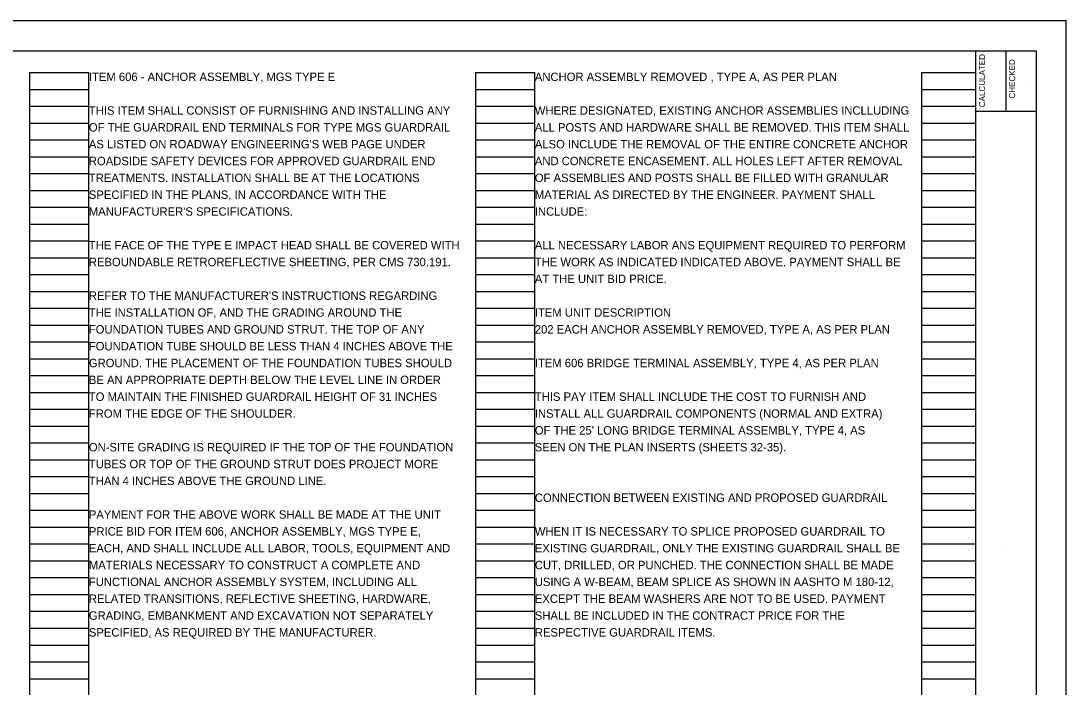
# Model space of a CAD drawing. Extents: x 0 to 34, y 0 to 22.
# Drawn here: x 16.61 to 34, y 10.92 to 22 of the extents above; entities that cross this region are included whole.
import ezdxf

# ---------------------------------------------------------------- set-up
doc = ezdxf.new("R2010")
doc.units = 0
for name, color, linetype in [('SH_Border', 7, 'Continuous'), ('SH_Cut_Line', 7, 'Continuous'), ('SH_Data', 7, 'Continuous'), ('SH_Text', 7, 'Continuous')]:
    doc.layers.add(name, color=color, linetype=linetype)

msp = doc.modelspace()

# ---------------------------------------------------------------- linework, layer by layer
at = {"layer": 'SH_Border'}
for p, q in [((32.5, 0.5), (32.5, 21.5)), ((33, 21.5), (33, 20.5)), ((32.5, 20.5), (33.5, 20.5))]:
    msp.add_line(p, q, dxfattribs=at)
msp.add_lwpolyline([(2, 21.5), (33.5, 21.5), (33.5, 0.5), (2, 0.5)], close=True, dxfattribs=at)
at = {"layer": 'SH_Cut_Line'}
msp.add_lwpolyline([(0, 0), (34, 0), (34, 22), (0, 22)], close=True, dxfattribs=at)
at = {"layer": 'SH_Data'}
for p, q in [((16.76, 0.98), (16.76, 21.14)), ((16.76, 21.14), (17.74, 21.14)), ((17.74, 0.98), (17.74, 21.14)), ((24.18, 0.98), (24.18, 21.14)), ((24.18, 21.14), (25.16, 21.14)), ((25.16, 0.98), (25.16, 21.14)), ((31.6, 0.98), (31.6, 21.14)), ((31.6, 21.14), (32.5, 21.14)), ((32.5, 0.98), (32.5, 21.14)), ((32.92, 21.004), (32.92, 21.004)), ((33.42, 21.004), (33.42, 21.004)), ((16.76, 20.86), (17.74, 20.86)), ((24.18, 20.86), (25.16, 20.86)), ((31.6, 20.86), (32.5, 20.86)), ((16.76, 20.58), (17.74, 20.58)), ((24.18, 20.58), (25.16, 20.58)), ((31.6, 20.58), (32.5, 20.58)), ((16.76, 20.3), (17.74, 20.3)), ((24.18, 20.3), (25.16, 20.3)), ((31.6, 20.3), (32.5, 20.3)), ((16.76, 20.02), (17.74, 20.02)), ((24.18, 20.02), (25.16, 20.02)), ((31.6, 20.02), (32.5, 20.02)), ((16.76, 19.74), (17.74, 19.74)), ((24.18, 19.74), (25.16, 19.74)), ((31.6, 19.74), (32.5, 19.74)), ((16.76, 19.46), (17.74, 19.46)), ((24.18, 19.46), (25.16, 19.46)), ((31.6, 19.46), (32.5, 19.46)), ((16.76, 19.18), (17.74, 19.18)), ((24.18, 19.18), (25.16, 19.18)), ((31.6, 19.18), (32.5, 19.18)), ((16.76, 18.9), (17.74, 18.9)), ((24.18, 18.9), (25.16, 18.9)), ((31.6, 18.9), (32.5, 18.9)), ((16.76, 18.62), (17.74, 18.62)), ((24.18, 18.62), (25.16, 18.62)), ((31.6, 18.62), (32.5, 18.62)), ((16.76, 18.34), (17.74, 18.34)), ((24.18, 18.34), (25.16, 18.34)), ((31.6, 18.34), (32.5, 18.34)), ((16.76, 18.06), (17.74, 18.06)), ((24.18, 18.06), (25.16, 18.06)), ((31.6, 18.06), (32.5, 18.06)), ((16.76, 17.78), (17.74, 17.78)), ((24.18, 17.78), (25.16, 17.78)), ((31.6, 17.78), (32.5, 17.78)), ((16.76, 17.5), (17.74, 17.5)), ((24.18, 17.5), (25.16, 17.5)), ((31.6, 17.5), (32.5, 17.5)), ((16.76, 17.22), (17.74, 17.22)), ((24.18, 17.22), (25.16, 17.22)), ((31.6, 17.22), (32.5, 17.22)), ((16.76, 16.94), (17.74, 16.94)), ((24.18, 16.94), (25.16, 16.94)), ((31.6, 16.94), (32.5, 16.94)), ((16.76, 16.66), (17.74, 16.66)), ((24.18, 16.66), (25.16, 16.66)), ((31.6, 16.66), (32.5, 16.66)), ((16.76, 16.38), (17.74, 16.38)), ((24.18, 16.38), (25.16, 16.38)), ((31.6, 16.38), (32.5, 16.38)), ((16.76, 16.1), (17.74, 16.1)), ((24.18, 16.1), (25.16, 16.1)), ((31.6, 16.1), (32.5, 16.1)), ((16.76, 15.82), (17.74, 15.82)), ((24.18, 15.82), (25.16, 15.82)), ((31.6, 15.82), (32.5, 15.82)), ((16.76, 15.54), (17.74, 15.54)), ((24.18, 15.54), (25.16, 15.54)), ((31.6, 15.54), (32.5, 15.54)), ((16.76, 15.26), (17.74, 15.26)), ((24.18, 15.26), (25.16, 15.26)), ((31.6, 15.26), (32.5, 15.26)), ((16.76, 14.98), (17.74, 14.98)), ((24.18, 14.98), (25.16, 14.98)), ((31.6, 14.98), (32.5, 14.98)), ((16.76, 14.7), (17.74, 14.7)), ((24.18, 14.7), (25.16, 14.7)), ((31.6, 14.7), (32.5, 14.7)), ((16.76, 14.42), (17.74, 14.42)), ((24.18, 14.42), (25.16, 14.42)), ((31.6, 14.42), (32.5, 14.42)), ((16.76, 14.14), (17.74, 14.14)), ((24.18, 14.14), (25.16, 14.14)), ((31.6, 14.14), (32.5, 14.14)), ((16.76, 13.86), (17.74, 13.86)), ((24.18, 13.86), (25.16, 13.86)), ((31.6, 13.86), (32.5, 13.86)), ((16.76, 13.58), (17.74, 13.58)), ((24.18, 13.58), (25.16, 13.58)), ((31.6, 13.58), (32.5, 13.58)), ((16.76, 13.3), (17.74, 13.3)), ((24.18, 13.3), (25.16, 13.3)), ((31.6, 13.3), (32.5, 13.3)), ((33, 13.292), (33, 13.292)), ((16.76, 13.02), (17.74, 13.02)), ((24.18, 13.02), (25.16, 13.02)), ((31.6, 13.02), (32.5, 13.02)), ((16.76, 12.74), (17.74, 12.74)), ((24.18, 12.74), (25.16, 12.74)), ((31.6, 12.74), (32.5, 12.74)), ((16.76, 12.46), (17.74, 12.46)), ((24.18, 12.46), (25.16, 12.46)), ((31.6, 12.46), (32.5, 12.46)), ((16.76, 12.18), (17.74, 12.18)), ((24.18, 12.18), (25.16, 12.18)), ((31.6, 12.18), (32.5, 12.18)), ((16.76, 11.9), (17.74, 11.9)), ((24.18, 11.9), (25.16, 11.9)), ((31.6, 11.9), (32.5, 11.9)), ((16.76, 11.62), (17.74, 11.62)), ((24.18, 11.62), (25.16, 11.62)), ((31.6, 11.62), (32.5, 11.62)), ((16.76, 11.34), (17.74, 11.34)), ((24.18, 11.34), (25.16, 11.34)), ((31.6, 11.34), (32.5, 11.34)), ((16.76, 11.06), (17.74, 11.06)), ((24.18, 11.06), (25.16, 11.06)), ((31.6, 11.06), (32.5, 11.06))]:
    msp.add_line(p, q, dxfattribs=at)

# ---------------------------------------------------------------- texts
for s, p in [('CALCULATED', (32.652, 20.565)), ('CHECKED', (33.152, 20.708))]:
    msp.add_text(s, height=0.1, rotation=90, dxfattribs=at).set_placement(p)
at = {"layer": 'SH_Text'}
for s, p in [('ITEM 606 - ANCHOR ASSEMBLY, MGS TYPE E', (17.74, 21)), ('ANCHOR ASSEMBLY REMOVED , TYPE A, AS PER PLAN', (25.16, 21)), ('THIS ITEM SHALL CONSIST OF FURNISHING AND INSTALLING ANY', (17.74, 20.44)), ('WHERE DESIGNATED, EXISTING ANCHOR ASSEMBLIES INCLLUDING', (25.16, 20.44)), ('OF THE GUARDRAIL END TERMINALS FOR TYPE MGS GUARDRAIL', (17.74, 20.16)), ('ALL POSTS AND HARDWARE SHALL BE REMOVED. THIS ITEM SHALL', (25.16, 20.16)), ("AS LISTED ON ROADWAY ENGINEERING'S WEB PAGE UNDER", (17.74, 19.88)), ('ALSO INCLUDE THE REMOVAL OF THE ENTIRE CONCRETE ANCHOR', (25.16, 19.88)), ('ROADSIDE SAFETY DEVICES FOR APPROVED GUARDRAIL END', (17.74, 19.6)), ('AND CONCRETE ENCASEMENT. ALL HOLES LEFT AFTER REMOVAL', (25.16, 19.6)), ('TREATMENTS. INSTALLATION SHALL BE AT THE LOCATIONS', (17.74, 19.32)), ('OF ASSEMBLIES AND POSTS SHALL BE FILLED WITH GRANULAR', (25.16, 19.32)), ('SPECIFIED IN THE PLANS, IN ACCORDANCE WITH THE', (17.74, 19.04)), ('MATERIAL AS DIRECTED BY THE ENGINEER. PAYMENT SHALL', (25.16, 19.04)), ("MANUFACTURER'S SPECIFICATIONS.", (17.74, 18.76)), ('INCLUDE:', (25.16, 18.76)), ('THE FACE OF THE TYPE E IMPACT HEAD SHALL BE COVERED WITH ', (17.74, 18.2)), ('ALL NECESSARY LABOR ANS EQUIPMENT REQUIRED TO PERFORM', (25.16, 18.2)), ('REBOUNDABLE RETROREFLECTIVE SHEETING, PER CMS 730.191.', (17.74, 17.92)), ('THE WORK AS INDICATED INDICATED ABOVE. PAYMENT SHALL BE', (25.16, 17.92)), ('AT THE UNIT BID PRICE.', (25.16, 17.64)), ("REFER TO THE MANUFACTURER'S INSTRUCTIONS REGARDING", (17.74, 17.36)), ('THE INSTALLATION OF, AND THE GRADING AROUND THE', (17.74, 17.08)), ('ITEM UNIT DESCRIPTION', (25.16, 17.08)), ('FOUNDATION TUBES AND GROUND STRUT. THE TOP OF ANY', (17.74, 16.8)), ('202 EACH ANCHOR ASSEMBLY REMOVED, TYPE A, AS PER PLAN', (25.16, 16.8)), ('FOUNDATION TUBE SHOULD BE LESS THAN 4 INCHES ABOVE THE', (17.74, 16.52)), ('GROUND. THE PLACEMENT OF THE FOUNDATION TUBES SHOULD', (17.74, 16.24)), ('ITEM 606 BRIDGE TERMINAL ASSEMBLY, TYPE 4, AS PER PLAN', (25.16, 16.24)), ('BE AN APPROPRIATE DEPTH BELOW THE LEVEL LINE IN ORDER', (17.74, 15.96)), ('TO MAINTAIN THE FINISHED GUARDRAIL HEIGHT OF 31 INCHES', (17.74, 15.68)), ('THIS PAY ITEM SHALL INCLUDE THE COST TO FURNISH AND', (25.16, 15.68)), ('FROM THE EDGE OF THE SHOULDER.', (17.74, 15.4)), ('INSTALL ALL GUARDRAIL COMPONENTS (NORMAL AND EXTRA)', (25.16, 15.4)), ("OF THE 25' LONG BRIDGE TERMINAL ASSEMBLY, TYPE 4, AS", (25.16, 15.12)), ('ON-SITE GRADING IS REQUIRED IF THE TOP OF THE FOUNDATION', (17.74, 14.84)), ('SEEN ON THE PLAN INSERTS (SHEETS 32-35).', (25.16, 14.84)), ('TUBES OR TOP OF THE GROUND STRUT DOES PROJECT MORE', (17.74, 14.56)), ('THAN 4 INCHES ABOVE THE GROUND LINE.', (17.74, 14.28)), ('CONNECTION BETWEEN EXISTING AND PROPOSED GUARDRAIL', (25.16, 14)), ('PAYMENT FOR THE ABOVE WORK SHALL BE MADE AT THE UNIT', (17.74, 13.72)), ('PRICE BID FOR ITEM 606, ANCHOR ASSEMBLY, MGS TYPE E,', (17.74, 13.44)), ('WHEN IT IS NECESSARY TO SPLICE PROPOSED GUARDRAIL TO', (25.16, 13.44)), ('EACH, AND SHALL INCLUDE ALL LABOR, TOOLS, EQUIPMENT AND', (17.74, 13.16)), ('EXISTING GUARDRAIL, ONLY THE EXISTING GUARDRAIL SHALL BE', (25.16, 13.16)), ('MATERIALS NECESSARY TO CONSTRUCT A COMPLETE AND', (17.74, 12.88)), ('CUT, DRILLED, OR PUNCHED. THE CONNECTION SHALL BE MADE', (25.16, 12.88)), ('FUNCTIONAL ANCHOR ASSEMBLY SYSTEM, INCLUDING ALL', (17.74, 12.6)), ('USING A W-BEAM, BEAM SPLICE AS SHOWN IN AASHTO M 180-12,', (25.16, 12.6)), ('RELATED TRANSITIONS, REFLECTIVE SHEETING, HARDWARE,', (17.74, 12.32)), ('EXCEPT THE BEAM WASHERS ARE NOT TO BE USED. PAYMENT', (25.16, 12.32)), ('GRADING, EMBANKMENT AND EXCAVATION NOT SEPARATELY', (17.74, 12.04)), ('SHALL BE INCLUDED IN THE CONTRACT PRICE FOR THE', (25.16, 12.04)), ('SPECIFIED, AS REQUIRED BY THE MANUFACTURER.', (17.74, 11.76)), ('RESPECTIVE GUARDRAIL ITEMS.', (25.16, 11.76))]:
    msp.add_text(s, height=0.14, dxfattribs=at).set_placement(p)

doc.saveas('drawing.dxf')
